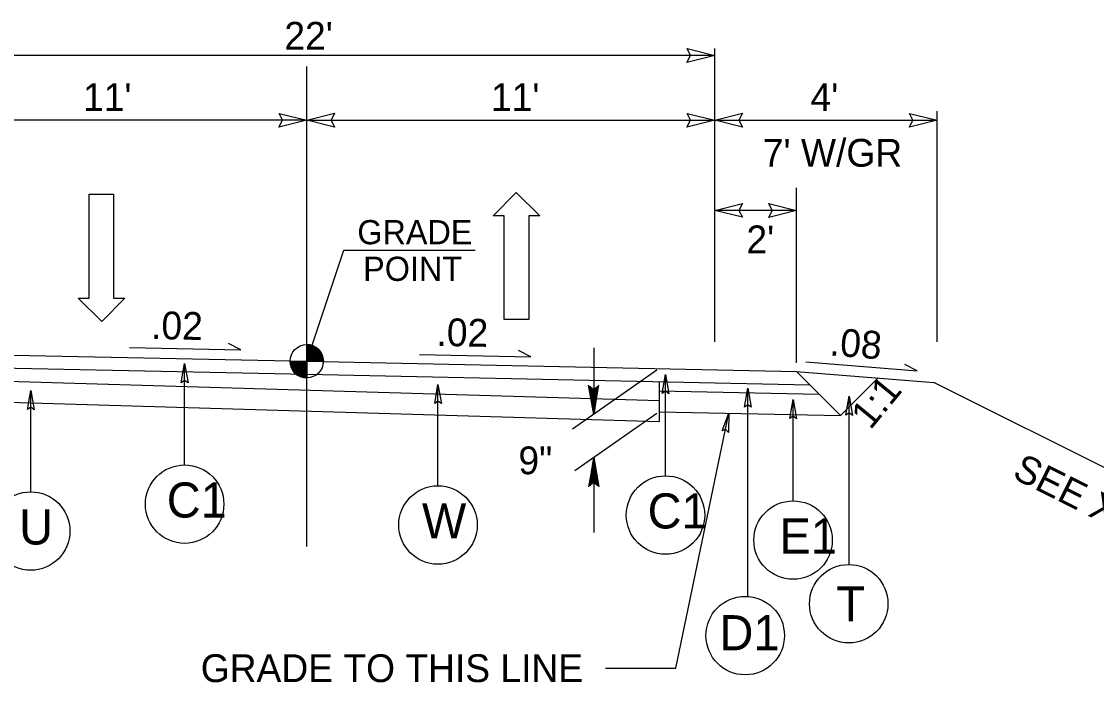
# Model space of a CAD drawing. Extents: x 575722 to 576066, y -53107 to -52774.
# Drawn here: x 575897.08 to 575926.06, y -52856.52 to -52838.69 of the extents above; entities that cross this region are included whole.
import ezdxf

# ---------------------------------------------------------------- set-up
doc = ezdxf.new("R2010")
doc.units = 0
for name, color, linetype in [('Prop Dimension Text', 7, 'Continuous'), ('Prop DSN Text', 7, 'Continuous'), ('Prop Lane Arrow CELL', 7, 'Continuous'), ('Prop Terminator CELL', 7, 'Continuous'), ('Typical Grade Point Symbol CELL', 7, 'Continuous'), ('Typical ID Circle CELL', 7, 'Continuous'), ('Typical Pavement Slope CELL', 7, 'Continuous'), ('Typical Slope Point Local CELL', 7, 'Continuous'), ('Typical Terminator CELL', 7, 'Continuous'), ('Typical Text Centerline CELL', 7, 'Continuous'), ('Typical Text Grade Point CELL', 7, 'Continuous'), ('Typical Text ID Circle CELL', 7, 'Continuous')]:
    doc.layers.add(name, color=color, linetype=linetype)

# ---------------------------------------------------------------- blocks, each defined once
blk = doc.blocks.new('TERMINATOR')
at = {"layer": 'Typical Terminator CELL'}
blk.add_lwpolyline([(-0.469, 0.081), (0, 0), (-0.471, -0.083), (-0.411, 0)], close=True, dxfattribs=at)

msp = doc.modelspace()

# ---------------------------------------------------------------- linework, layer by layer
at = {"layer": 'Prop Dimension Text'}
for p, q in [((575915.77, -52839.605), (575893.77, -52839.605)), ((575915.77, -52847.332), (575915.77, -52839.415)), ((575915.77, -52847.332), (575915.77, -52841.102)), ((575915.77, -52846.852), (575915.77, -52841.102)), ((575915.77, -52846.852), (575915.77, -52841.102)), ((575915.77, -52846.852), (575915.77, -52841.102)), ((575921.77, -52847.332), (575921.77, -52841.102)), ((575921.77, -52846.852), (575921.77, -52841.102)), ((575904.77, -52841.352), (575893.77, -52841.352)), ((575904.77, -52841.352), (575915.77, -52841.352)), ((575915.77, -52841.352), (575921.77, -52841.352)), ((575917.976, -52847.89), (575917.976, -52843.178)), ((575917.976, -52843.784), (575915.77, -52843.784)), ((575915.782, -52848.083), (575915.777, -52848.088)), ((575919.163, -52849.318), (575917.971, -52848.126)), ((575919.163, -52849.318), (575920.178, -52848.303))]:
    msp.add_line(p, q, dxfattribs=at)
at = {"layer": 'Prop DSN Text'}
for p, q in [((575912.508, -52847.49), (575912.508, -52849.285)), ((575914.213, -52848.091), (575911.935, -52849.686)), ((575912.508, -52849.285), (575912.369, -52848.498)), ((575912.508, -52849.285), (575912.389, -52848.513)), ((575912.408, -52848.528), (575912.508, -52849.285)), ((575912.508, -52849.285), (575912.428, -52848.542)), ((575912.449, -52848.557), (575912.508, -52849.285)), ((575912.508, -52849.285), (575912.468, -52848.571)), ((575912.488, -52848.586), (575912.508, -52849.285)), ((575912.508, -52849.285), (575912.648, -52848.498)), ((575912.628, -52848.513), (575912.508, -52849.285)), ((575912.508, -52849.285), (575912.606, -52848.528)), ((575912.586, -52848.542), (575912.508, -52849.285)), ((575912.508, -52849.285), (575912.567, -52848.557)), ((575912.547, -52848.571), (575912.508, -52849.285)), ((575912.508, -52849.285), (575912.527, -52848.586)), ((575912.508, -52848.601), (575912.508, -52849.285)), ((575914.213, -52849.258), (575912, -52850.807)), ((575914.724, -52856.128), (575916.155, -52849.255)), ((575912.508, -52850.452), (575912.369, -52851.239)), ((575912.389, -52851.224), (575912.508, -52850.452)), ((575912.508, -52850.452), (575912.408, -52851.21)), ((575912.428, -52851.194), (575912.508, -52850.452)), ((575912.508, -52850.452), (575912.449, -52851.18)), ((575912.468, -52851.167), (575912.508, -52850.452)), ((575912.508, -52850.452), (575912.488, -52851.152)), ((575912.508, -52850.452), (575912.508, -52852.473)), ((575912.508, -52850.452), (575912.648, -52851.239)), ((575912.508, -52851.137), (575912.508, -52850.452)), ((575912.527, -52851.152), (575912.508, -52850.452)), ((575912.508, -52850.452), (575912.547, -52851.167)), ((575912.567, -52851.18), (575912.508, -52850.452)), ((575912.508, -52850.452), (575912.586, -52851.194)), ((575912.606, -52851.21), (575912.508, -52850.452)), ((575912.508, -52850.452), (575912.628, -52851.224)), ((575912.823, -52856.128), (575914.724, -52856.128))]:
    msp.add_line(p, q, dxfattribs=at)
at = {"layer": 'Prop Lane Arrow CELL'}
for p, q in [((575898.902, -52846.146), (575898.902, -52843.346)), ((575898.902, -52843.346), (575899.562, -52843.346)), ((575899.562, -52843.346), (575899.562, -52846.146)), ((575909.795, -52843.927), (575910.415, -52843.297)), ((575910.415, -52843.297), (575911.055, -52843.927)), ((575910.095, -52843.927), (575909.795, -52843.927)), ((575910.095, -52846.727), (575910.095, -52843.927)), ((575911.055, -52843.927), (575910.755, -52843.927)), ((575910.755, -52843.927), (575910.755, -52846.727)), ((575899.242, -52846.776), (575898.602, -52846.146)), ((575898.602, -52846.146), (575898.902, -52846.146)), ((575899.862, -52846.146), (575899.242, -52846.776)), ((575899.562, -52846.146), (575899.862, -52846.146)), ((575910.755, -52846.727), (575910.095, -52846.727))]:
    msp.add_line(p, q, dxfattribs=at)
at = {"layer": 'Prop Terminator CELL'}
msp.add_lwpolyline([(575915.968, -52849.731), (575916.155, -52849.255), (575916.14, -52849.77), (575916.065, -52849.688)], close=True, dxfattribs=at)
msp.add_lwpolyline([(575915.968, -52849.731), (575916.155, -52849.255), (575916.14, -52849.77), (575916.065, -52849.688)], close=True, dxfattribs=at)
at = {"layer": 'Typical Grade Point Symbol CELL'}
for p, q in [((575904.77, -52847.852), (575905.77, -52844.852)), ((575904.77, -52847.852), (575904.77, -52847.404)), ((575904.322, -52847.852), (575904.77, -52847.852)), ((575904.769, -52848.299), (575904.77, -52847.852)), ((575904.77, -52847.852), (575904.769, -52848.299)), ((575905.217, -52847.852), (575904.77, -52847.852))]:
    msp.add_line(p, q, dxfattribs=at)
for points in [[(575904.774, -52847.404), (575904.774, -52847.404), (575904.774, -52847.852)], [(575904.783, -52847.404), (575904.783, -52847.852)], [(575904.792, -52847.405), (575904.792, -52847.852)], [(575904.8, -52847.405), (575904.8, -52847.852)], [(575904.809, -52847.406), (575904.809, -52847.852)], [(575904.818, -52847.407), (575904.818, -52847.852)], [(575904.827, -52847.408), (575904.827, -52847.852)], [(575904.836, -52847.409), (575904.836, -52847.852)], [(575904.845, -52847.41), (575904.845, -52847.852)], [(575904.854, -52847.412), (575904.854, -52847.852)], [(575904.863, -52847.414), (575904.863, -52847.852)], [(575904.872, -52847.416), (575904.872, -52847.852)], [(575904.881, -52847.418), (575904.881, -52847.852)], [(575904.89, -52847.421), (575904.89, -52847.852)], [(575904.899, -52847.423), (575904.899, -52847.852)], [(575904.908, -52847.426), (575904.908, -52847.852)], [(575904.917, -52847.429), (575904.917, -52847.852)], [(575904.926, -52847.432), (575904.926, -52847.852)], [(575904.935, -52847.436), (575904.935, -52847.852)], [(575904.944, -52847.44), (575904.944, -52847.852)], [(575904.953, -52847.444), (575904.953, -52847.852)], [(575904.962, -52847.448), (575904.962, -52847.852)], [(575904.971, -52847.452), (575904.971, -52847.852)], [(575904.98, -52847.457), (575904.98, -52847.852)], [(575904.988, -52847.462), (575904.988, -52847.852)], [(575904.997, -52847.467), (575904.997, -52847.852)], [(575905.006, -52847.472), (575905.006, -52847.852)], [(575905.015, -52847.478), (575905.015, -52847.852)], [(575905.024, -52847.484), (575905.024, -52847.852)], [(575905.033, -52847.491), (575905.033, -52847.852)], [(575905.042, -52847.497), (575905.042, -52847.852)], [(575905.051, -52847.504), (575905.051, -52847.852)], [(575905.06, -52847.511), (575905.06, -52847.852)], [(575905.069, -52847.519), (575905.069, -52847.852)], [(575905.078, -52847.527), (575905.078, -52847.852)], [(575905.087, -52847.536), (575905.087, -52847.852)], [(575905.096, -52847.545), (575905.096, -52847.852)], [(575905.105, -52847.555), (575905.105, -52847.852)], [(575905.114, -52847.566), (575905.114, -52847.852)], [(575905.123, -52847.577), (575905.123, -52847.852)], [(575905.132, -52847.589), (575905.132, -52847.852)], [(575905.141, -52847.602), (575905.141, -52847.852)], [(575905.15, -52847.616), (575905.15, -52847.852)], [(575905.159, -52847.631), (575905.159, -52847.852)], [(575905.168, -52847.647), (575905.168, -52847.852)], [(575905.176, -52847.666), (575905.176, -52847.852)], [(575905.185, -52847.687), (575905.185, -52847.852)], [(575905.194, -52847.711), (575905.194, -52847.852)], [(575905.203, -52847.742), (575905.203, -52847.852)], [(575905.212, -52847.788), (575905.212, -52847.852)], [(575904.324, -52847.852), (575904.324, -52847.9)], [(575904.333, -52847.852), (575904.333, -52847.953)], [(575904.342, -52847.852), (575904.342, -52847.985)], [(575904.351, -52847.852), (575904.351, -52848.012)], [(575904.36, -52847.852), (575904.36, -52848.033)], [(575904.369, -52847.852), (575904.369, -52848.052)], [(575904.378, -52847.852), (575904.378, -52848.068)], [(575904.387, -52847.852), (575904.387, -52848.084)], [(575904.396, -52847.852), (575904.396, -52848.098)], [(575904.405, -52847.852), (575904.405, -52848.111)], [(575904.414, -52847.852), (575904.414, -52848.123)], [(575904.423, -52847.852), (575904.423, -52848.134)], [(575904.431, -52847.852), (575904.431, -52848.145)], [(575904.44, -52847.852), (575904.44, -52848.155)], [(575904.449, -52847.852), (575904.449, -52848.165)], [(575904.458, -52847.852), (575904.458, -52848.174)], [(575904.467, -52847.852), (575904.467, -52848.182)], [(575904.476, -52847.852), (575904.476, -52848.19)], [(575904.485, -52847.852), (575904.485, -52848.198)], [(575904.494, -52847.852), (575904.494, -52848.205)], [(575904.503, -52847.852), (575904.503, -52848.212)], [(575904.512, -52847.852), (575904.512, -52848.218)], [(575904.521, -52847.852), (575904.521, -52848.224)], [(575904.53, -52847.852), (575904.53, -52848.23)], [(575904.539, -52847.852), (575904.539, -52848.236)], [(575904.548, -52847.852), (575904.548, -52848.241)], [(575904.557, -52847.852), (575904.557, -52848.246)], [(575904.566, -52847.852), (575904.566, -52848.251)], [(575904.575, -52847.852), (575904.575, -52848.254)], [(575904.584, -52847.852), (575904.584, -52848.259)], [(575904.593, -52847.852), (575904.593, -52848.262)], [(575904.602, -52847.852), (575904.602, -52848.266)], [(575904.611, -52847.852), (575904.611, -52848.27)], [(575904.619, -52847.852), (575904.619, -52848.273)], [(575904.628, -52847.852), (575904.628, -52848.276)], [(575904.637, -52847.852), (575904.637, -52848.279)], [(575904.646, -52847.852), (575904.646, -52848.281)], [(575904.655, -52847.852), (575904.655, -52848.284)], [(575904.664, -52847.852), (575904.664, -52848.286)], [(575904.673, -52847.852), (575904.673, -52848.288)], [(575904.682, -52847.852), (575904.682, -52848.29)], [(575904.691, -52847.852), (575904.691, -52848.292)], [(575904.7, -52847.852), (575904.7, -52848.293)], [(575904.709, -52847.852), (575904.709, -52848.295)], [(575904.718, -52847.852), (575904.718, -52848.296)], [(575904.727, -52847.852), (575904.727, -52848.297)], [(575904.736, -52847.852), (575904.736, -52848.298)], [(575904.745, -52847.852), (575904.745, -52848.298)], [(575904.754, -52847.852), (575904.754, -52848.299)], [(575904.763, -52847.852), (575904.763, -52848.299), (575904.763, -52848.299)]]:
    msp.add_lwpolyline(points, dxfattribs=at)
msp.add_circle((575904.769, -52847.852), 0.448, dxfattribs=at)
for start, end in [(359.9905, 89.9905), (179.9905, 269.9905)]:
    msp.add_arc((575904.769, -52847.852), 0.448, start, end, dxfattribs=at)
at = {"layer": 'Typical ID Circle CELL'}
for p, q in [((575901.477, -52850.648), (575901.477, -52847.914)), ((575914.443, -52850.942), (575914.443, -52848.208)), ((575897.327, -52851.374), (575897.327, -52848.64)), ((575908.308, -52851.21), (575908.308, -52848.476)), ((575916.66, -52854.195), (575916.66, -52848.575)), ((575917.883, -52851.619), (575917.883, -52848.885)), ((575919.391, -52853.334), (575919.391, -52848.794))]:
    msp.add_line(p, q, dxfattribs=at)
for centre in [(575901.477, -52851.706), (575914.443, -52852), (575908.308, -52852.268), (575897.327, -52852.432), (575917.883, -52852.676), (575919.384, -52854.392), (575916.592, -52855.251)]:
    msp.add_circle(centre, 1.058, dxfattribs=at)
at = {"layer": 'Typical Pavement Slope CELL'}
for p, q in [((575899.992, -52847.481), (575902.992, -52847.543)), ((575902.992, -52847.543), (575902.659, -52847.376)), ((575907.811, -52847.666), (575910.811, -52847.728)), ((575910.811, -52847.728), (575910.477, -52847.562)), ((575918.231, -52847.867), (575921.231, -52848.107)), ((575921.231, -52848.107), (575920.898, -52847.941)), ((575917.971, -52848.126), (575921.682, -52848.423)), ((575914.272, -52848.399), (575914.272, -52849.216)), ((575914.272, -52848.913), (575914.272, -52849.48))]:
    msp.add_line(p, q, dxfattribs=at)
for points in [[(575891.568, -52847.577), (575904.77, -52847.852)], [(575891.225, -52847.92), (575904.77, -52848.202)], [(575904.77, -52847.852), (575917.971, -52848.126)], [(575890.932, -52848.214), (575914.272, -52848.913)], [(575904.77, -52848.202), (575918.329, -52848.484)], [(575914.272, -52848.649), (575918.584, -52848.739)], [(575890.376, -52848.769), (575914.272, -52849.48)], [(575914.272, -52849.216), (575919.163, -52849.318)]]:
    msp.add_lwpolyline(points, dxfattribs=at)
at = {"layer": 'Typical Slope Point Local CELL'}
msp.add_line((575932.845, -52854.005), (575921.682, -52848.423), dxfattribs=at)
at = {"layer": 'Typical Terminator CELL'}
for points in [[(575901.388, -52848.43), (575901.477, -52847.914), (575901.569, -52848.433), (575901.477, -52848.367)], [(575914.354, -52848.724), (575914.443, -52848.208), (575914.534, -52848.726), (575914.443, -52848.661)], [(575897.238, -52849.156), (575897.327, -52848.64), (575897.419, -52849.159), (575897.327, -52849.093)], [(575908.219, -52848.992), (575908.308, -52848.476), (575908.399, -52848.995), (575908.308, -52848.929)], [(575916.572, -52849.091), (575916.66, -52848.575), (575916.752, -52849.094), (575916.66, -52849.028)], [(575917.794, -52849.4), (575917.883, -52848.885), (575917.975, -52849.403), (575917.883, -52849.337)], [(575919.302, -52849.309), (575919.391, -52848.794), (575919.482, -52849.312), (575919.391, -52849.246)]]:
    msp.add_lwpolyline(points, close=True, dxfattribs=at)
at = {"layer": 'Typical Text Centerline CELL'}
msp.add_line((575904.77, -52852.852), (575904.77, -52839.903), dxfattribs=at)
at = {"layer": 'Typical Text Grade Point CELL'}
msp.add_line((575905.77, -52844.852), (575909.308, -52844.852), dxfattribs=at)

# ---------------------------------------------------------------- block references
at = {"layer": 'Prop Dimension Text', "xscale": 1.5906680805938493, "yscale": 2.2831050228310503}
for p in [(575915.77, -52839.605), (575904.77, -52841.352), (575915.77, -52841.352), (575921.77, -52841.352), (575917.976, -52843.784)]:
    msp.add_blockref('TERMINATOR', p, dxfattribs=at)
at = {"layer": 'Prop Dimension Text', "xscale": 1.5906680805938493, "yscale": 2.2831050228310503, "rotation": 180}
for p in [(575904.77, -52841.352), (575915.77, -52841.352), (575915.77, -52843.784)]:
    msp.add_blockref('TERMINATOR', p, dxfattribs=at)

# ---------------------------------------------------------------- texts
at = {"layer": 'Prop Dimension Text'}
for s, p in [("22'", (575904.166, -52839.448)), ("11'", (575898.737, -52841.102)), ("11'", (575909.737, -52841.102)), ("4'", (575918.354, -52841.102)), ("7' W/GR", (575917.067, -52842.604)), ("2'", (575916.625, -52844.94))]:
    msp.add_text(s, height=0.75, dxfattribs=at).set_placement(p)
for s, rotation, p in [('.02', 358.8084, (575900.567, -52847.251)), ('.02', 358.8084, (575908.262, -52847.436)), ('.08', 355.4261, (575918.853, -52847.691))]:
    msp.add_text(s, height=0.75, rotation=rotation, dxfattribs=at).set_placement(p)
at = {"layer": 'Prop DSN Text'}
for s, p in [('9" ', (575910.477, -52850.9)), ('GRADE TO THIS LINE', (575901.912, -52856.506))]:
    msp.add_text(s, height=0.75, dxfattribs=at).set_placement(p)
at = {"layer": 'Typical Slope Point Local CELL'}
for s, rotation, p in [('1:1', 50.5662, (575919.967, -52849.724)), ('SEE X-SECTIONS', 333.434, (575923.763, -52850.986))]:
    msp.add_text(s, height=0.75, rotation=rotation, dxfattribs=at).set_placement(p)
at = {"layer": 'Typical Text Grade Point CELL'}
for s, p in [('GRADE', (575906.134, -52844.696)), ('POINT', (575906.291, -52845.684))]:
    msp.add_text(s, height=0.6525, dxfattribs=at).set_placement(p)
at = {"layer": 'Typical Text ID Circle CELL'}
for s, height, p in [('C1', 0.9469, (575900.995, -52852.068)), ('C1', 0.9469, (575913.961, -52852.362)), ('U', 0.947, (575897.016, -52852.795)), ('W', 0.947, (575907.876, -52852.631)), ('E1', 0.9469, (575917.516, -52853.039)), ('T', 0.947, (575919.05, -52854.871)), ('D1', 0.9469, (575915.898, -52855.647))]:
    msp.add_text(s, height=height, dxfattribs=at).set_placement(p)

doc.saveas('drawing.dxf')
